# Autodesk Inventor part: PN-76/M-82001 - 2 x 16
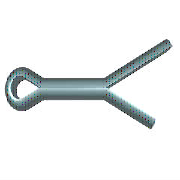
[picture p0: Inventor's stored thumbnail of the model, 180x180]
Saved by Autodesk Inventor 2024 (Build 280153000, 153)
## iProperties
Company: ATC
IsCustomPart: 0
Created: 2023-03
Part Number: PN-76/M-82001 - 2 x 16
Material: Stal, miękka
Description: Zawleczki
Document SubType Name: Modeling
Standard: PN-76/M-82001
Designer: Andrzej Jaskulski
Standards Organization: PN
Language: pl-PL
Size Designation: 2 x 16
Categories: <MemberInstance><Categories><Category DisplayName="Mocowania" InternalName="e4da775c-781d-43d5-af7c-5136215cf5a6" Mnemonic="FSTN"><Category DisplayName="Kołki"
Density: 7.85 g/cm^3
Appearance: Częściowo polerowany
Checked By: A.J.
Engr Approved By: Andrzej Jaskulski
Mfg Approved By: Andrzej Jaskulski
Authority: A.J.
Author: Andrzej Jaskulski
Title: A.J.: Kurs R2024-MEP
Revision Number: 1/24
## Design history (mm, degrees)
sketch "Szkic1"
  geometry: L1 (0, 0.85)-(8.5, 0.85); L2 (0, -0.85)-(8.5, -0.85); L3 (8.5, 0.85)-(16, 3.723); L4 (16, 3.723)-(16.284, 2.982); L5 (16.284, 2.982)-(8.5, 0); L6 (8.5, 0)-(18.784, -3.94); L7 (18.784, -3.94)-(18.5, -4.681); L8 (18.5, -4.681)-(8.5, -0.85); L9 (0, 0)-(-1.79, -0.857); L10 (0, 0)-(-1.79, 0.857); L11 (0, 0.85)-(0, -0.85); L12 (0, 0.85)-(-1.338, 1.58); L13 (0, -0.85)-(-1.338, -1.58); L14 (-4, 0)-(8.5, 0); L15 (8.5, 0.85)-(8.5, -0.85); A1 r 1.8 centre (-2.2, 0) between (-1.338, 1.58) and (-1.338, -1.58); A2 r 0.95 centre (-2.2, 0) between (-1.79, 0.857) and (-1.79, -0.857); 1 further point
  constraints: 30 end point, 5 point on circle, 4 parallel, 4 perpendicular, 4 point on line, 4 tangent, 2 centre point, 2 midpoint, 1 coincident, 1 horizontal
  dimensions: "d0" = 8.5 distance of L1.start L1.end (= MSIAB); "d1" = 16 horizontal distance of L1.start L3.end (= SNLG); "d2" = 159.037 deg angle of L1 L3; "d3" = 159.037 deg angle of L2 L8; "d4" = 2.5 horizontal distance of L3.end L7.end (= LGDIF); "d5" = 0.95 radius of A2 (= -0.5 x SNND1 + 0.5 x KBR); "d6" = 1.8 radius of A1 (= 0.5 x KBR); "d7" = 0.85 distance from line of L1 L9.start (= 0.5 x SNND1); "d8" = 0.85 distance between parallel lines of L2 L14 (= 0.5 x SNND1); "d9" = 2.2 distance from line of L11 A1.centre (= KOL - 0.5 x KBR)
extrude "Bryła" new body sketch "Szkic1" stored distance "d10" = 1.7 (= SNND1); taper "d11" = 0 deg
workaxis "Work Axis1"
workplane "Work Plane1"
workplane "Work Plane3"
node "Bryła1"
node "Korpusy bryłowe"
node "Korpusy powierzchniowe"
fillet "Zaokrąglenie" dims "d12" = 0.595 (= 0.35 x SNND1)
other parameters: "SNND" = 2 [user parameter], "SNLG" = 16 [user parameter; used in 1 equation term], "SNND1" = 1.7 [user parameter; used in 5 equation terms], "KBR" = 3.6 [user parameter; used in 3 equation terms], "KOL" = 4 [user parameter; used in 1 equation term], "LGDIF" = 2.5 [user parameter; used in 1 equation term], "MSIAB" = 8.5 [user parameter; used in 1 equation term], "d15" = 0, "d16" = 0, "d17" = 0, "NNDMAX" = 9 [user parameter], "DSH" = 4 [user parameter], "NNDMIN" = 7 [user parameter]
